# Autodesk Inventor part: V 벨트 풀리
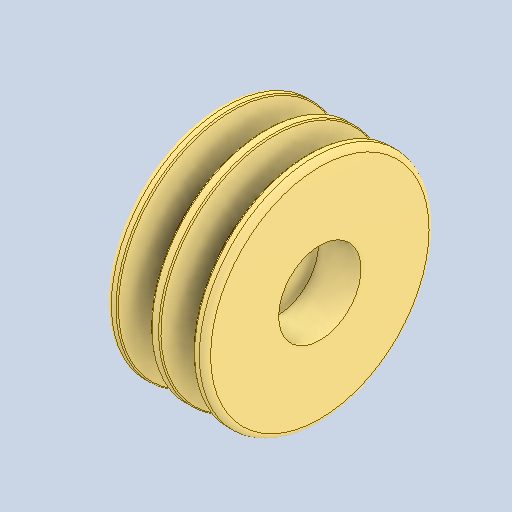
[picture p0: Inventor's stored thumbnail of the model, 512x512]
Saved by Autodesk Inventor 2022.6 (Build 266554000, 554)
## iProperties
Created: 2024-09
Part Number: V 벨트 풀리
Material: 강철, 주조
Document SubType Name: Modeling
Designer: Class 001
Density: 7.85 g/cm^3
Appearance: 기본값
Author: jhkim
Sending System: Autodesk Inventor 2025
Preprocessor: ST-DEVELOPER v20
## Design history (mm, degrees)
feature "솔리드1"
node "솔리드2"
